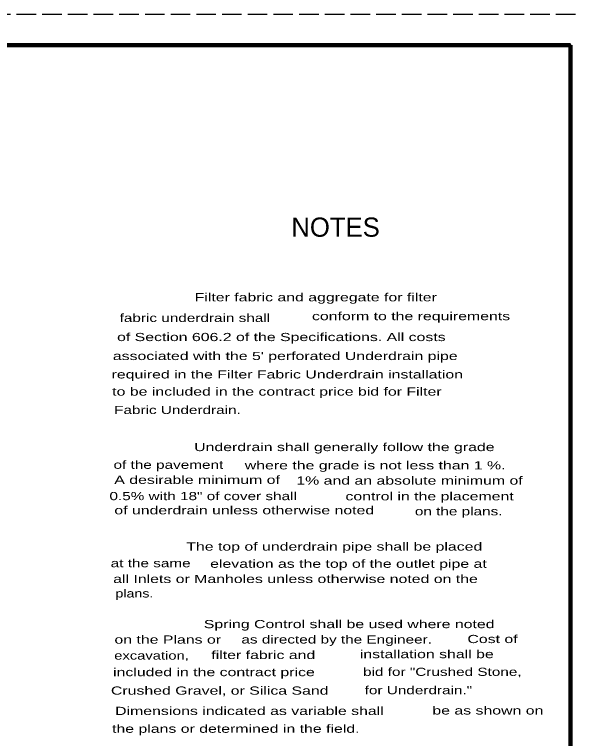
# Model space of a CAD drawing. Extents: x 36 to 71.3, y 0.3 to 22.3.
# Drawn here: x 62.04 to 71.17, y 10.54 to 22.32 of the extents above; entities that cross this region are included whole.
import ezdxf

# ---------------------------------------------------------------- set-up
doc = ezdxf.new("R2010")
doc.units = 0
doc.header["$LTSCALE"] = 0.053
doc.header["$PDMODE"] = 32
doc.header["$PDSIZE"] = 0.0265
doc.linetypes.add('LONG_DASHED', pattern=[7.5, 6, -1.5])
doc.layers.add('1', color=7, linetype='Continuous', lineweight=13)
doc.layers.add('2', color=7, linetype='Continuous', lineweight=13)

msp = doc.modelspace()

# ---------------------------------------------------------------- linework, layer by layer
at = {"layer": '1', "linetype": 'LONG_DASHED', "lineweight": 25}
msp.add_line((71.17325, 22.32408), (35.97325, 22.32408), dxfattribs=at)
at = {"layer": '1', "lineweight": 158}
for p, q in [((65.01858, 21.82408), (52.503, 21.82408)), ((71.08992, 21.82408), (65.01858, 21.82408))]:
    msp.add_line(p, q, dxfattribs=at)
msp.add_lwpolyline([(71.08992, 21.82408), (71.08992, 0.82408), (38.58992, 0.82408)], dxfattribs=at)
at = {"layer": '1'}
msp.add_point((71.08992, 21.82408), dxfattribs=at)

# ---------------------------------------------------------------- texts
at = {"layer": '1', "width": 1.45}
for s, p in [('be as shown on ', (68.84358, 10.93267)), (' the plans or determined in the field.', (63.55858, 10.6355))]:
    msp.add_text(s, height=0.133, dxfattribs=at).set_placement(p)
at = {"layer": '2'}
msp.add_text('NOTES', height=0.3125, dxfattribs=at).set_placement((66.54875, 18.70733))
for s, width, p in [('   Filter fabric and aggregate for filter ', 1.45, (64.76, 17.65667)), (' fabric underdrain shall', 1.4, (63.68483, 17.32058)), ('conform to the requirements ', 1.45, (66.88433, 17.34917)), ('of Section 606.2 of the Specifications. All costs', 1.45, (63.71242, 17.00933)), ("associated with the 5' perforated Underdrain pipe ", 1.45, (63.6435, 16.70075)), ('required in the Filter Fabric Underdrain installation ', 1.45, (63.62283, 16.40108)), ('to be included in the contract price bid for Filter ', 1.45, (63.63317, 16.12208)), ('Fabric Underdrain.', 1.4, (63.66417, 15.8225)), ('   Underdrain shall generally follow the grade ', 1.45, (64.752, 15.219)), ('of the pavement', 1.4, (63.65517, 14.93067)), ('where the grade is not less than 1 %.', 1.45, (65.79083, 14.92133)), ('A desirable minimum of', 1.45, (63.66758, 14.68567)), ('1% and an absolute minimum of ', 1.45, (66.62975, 14.67383)), (' 0.5% with 18" of cover shall', 1.4, (63.51942, 14.42083)), ('control in the placement', 1.45, (67.42917, 14.41758)), ('of underdrain unless otherwise noted', 1.45, (63.6675, 14.19042)), ('on the plans.', 1.4, (68.55867, 14.17375)), ('   The top of underdrain pipe shall be placed', 1.45, (64.62375, 13.6)), (' at the same', 1.4, (63.53917, 13.32975)), ('elevation as the top of the outlet pipe at', 1.45, (65.227, 13.32033)), ('all Inlets or Manholes unless otherwise noted on the ', 1.45, (63.64867, 13.07275)), ('plans.', 1.3, (63.686, 12.83708)), ('Spring Control shall be used where noted', 1.45, (65.12433, 12.338)), ('on the Plans or ', 1.45, (63.66967, 12.08625)), ('as directed by the Engineer.', 1.4, (65.736, 12.08792)), (' Cost of ', 1.45, (69.34225, 12.09525)), ('excavation,', 1.35, (63.66608, 11.82633)), ('filter fabric and', 1.45, (65.24633, 11.83542)), ('installation shall be ', 1.45, (67.66317, 11.84967)), ('included in the contract price ', 1.45, (63.64708, 11.5565)), ('bid for "Crushed Stone,', 1.4, (67.71583, 11.56117)), (' Crushed Gravel, or Silica Sand', 1.45, (63.54108, 11.25583)), ('for Underdrain."', 1.4, (67.74192, 11.26292)), ('Dimensions indicated as variable shall ', 1.45, (63.68025, 10.92517))]:
    msp.add_text(s, height=0.133, dxfattribs=dict(at, width=width)).set_placement(p)

doc.saveas('drawing.dxf')
